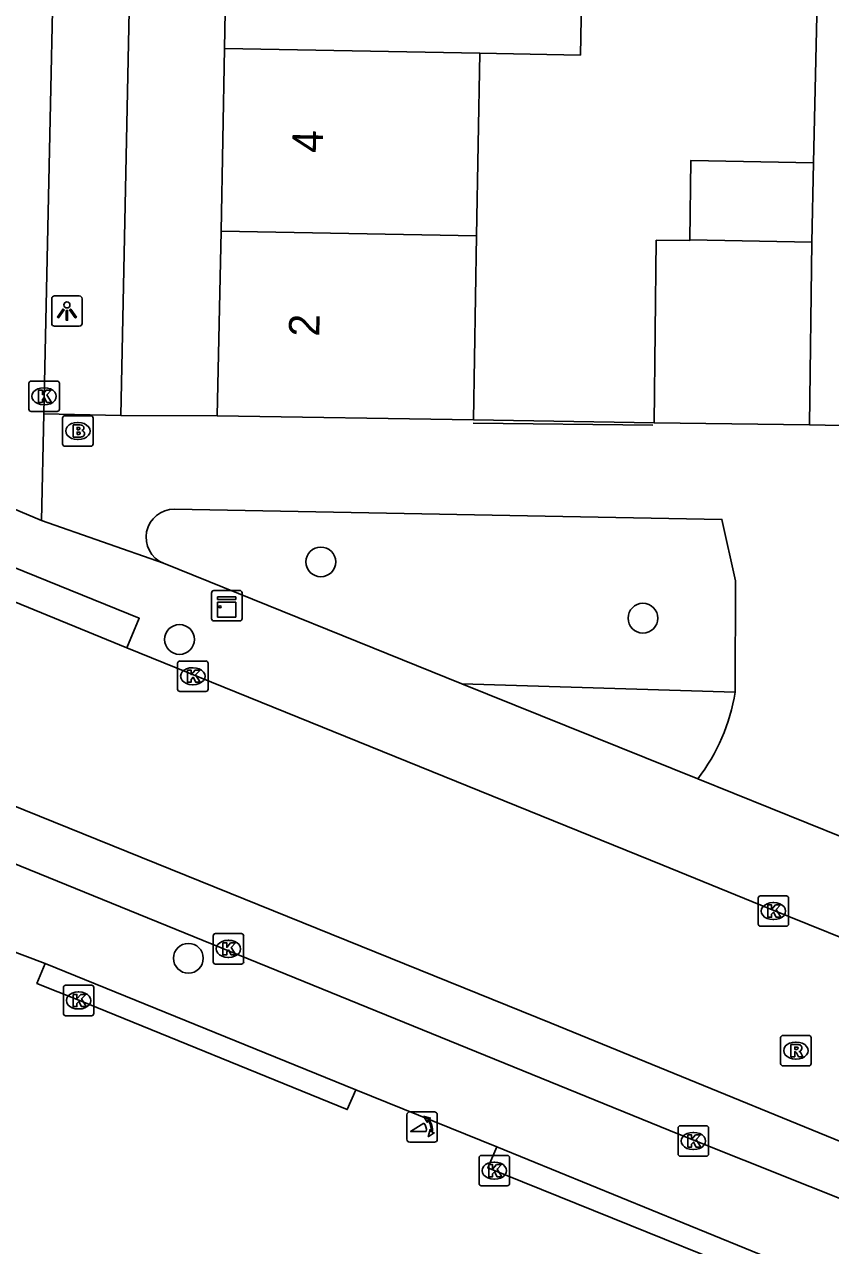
# Model space of a CAD drawing. Extents: x 160026 to 161302, y 384757 to 385701.
# Drawn here: x 160621.17 to 160647.62, y 385019.42 to 385059.5 of the extents above; entities that cross this region are included whole.
import ezdxf

# ---------------------------------------------------------------- set-up
doc = ezdxf.new("R2010")
doc.units = 0
for name, color, linetype in [('IMGEO_Boom', 7, 'Continuous'), ('IMGEO_Brandkraan', 7, 'Continuous'), ('IMGEO_Groenvoorziening', 7, 'Continuous'), ('IMGEO_Haag', 7, 'Continuous'), ('IMGEO_Kast', 7, 'Continuous'), ('IMGEO_Kolk', 7, 'Continuous'), ('IMGEO_Lichtpunt', 7, 'Continuous'), ('IMGEO_Muur', 7, 'Continuous'), ('IMGEO_Pand', 7, 'Continuous'), ('IMGEO_Pand_nummerreeks', 7, 'Continuous'), ('IMGEO_Poller', 7, 'Continuous'), ('IMGEO_Rijbaan_lokaal_gesloten', 7, 'Continuous'), ('IMGEO_Rijbaan_lokaal_open', 7, 'Continuous'), ('IMGEO_Rioolput', 7, 'Continuous'), ('IMGEO_Voetpad_open', 7, 'Continuous')]:
    doc.layers.add(name, color=color, linetype=linetype)

msp = doc.modelspace()

# ---------------------------------------------------------------- linework, layer by layer
at = {"layer": 'IMGEO_Boom'}
for centre in [(160630.895, 385041.857), (160641.464, 385040.01), (160626.26, 385039.312), (160626.55, 385028.846)]:
    msp.add_circle(centre, 0.489, dxfattribs=at)
at = {"layer": 'IMGEO_Brandkraan'}
for p, q in [((160622.425, 385045.729), (160622.425, 385046.581)), ((160622.5, 385046.655), (160623.352, 385046.655)), ((160623.426, 385046.581), (160623.426, 385045.729)), ((160622.913, 385046.435), (160622.938, 385046.435)), ((160622.936, 385045.875), (160622.911, 385045.875)), ((160623.352, 385045.655), (160622.5, 385045.655))]:
    msp.add_line(p, q, dxfattribs=at)
for points in [[(160622.425, 385045.729), (160622.425, 385046.581)], [(160622.5, 385046.655), (160623.352, 385046.655)], [(160623.426, 385046.581), (160623.426, 385045.729)], [(160622.773, 385046.355), (160622.773, 385045.955), (160622.986, 385045.955)], [(160623.004, 385046.355), (160622.773, 385046.355)], [(160622.952, 385046.274), (160622.898, 385046.274), (160622.898, 385046.198)], [(160622.898, 385046.198), (160622.951, 385046.198)], [(160622.96, 385046.122), (160622.898, 385046.122), (160622.898, 385046.041)], [(160622.898, 385046.041), (160622.96, 385046.041)], [(160623.352, 385045.655), (160622.5, 385045.655)]]:
    msp.add_lwpolyline(points, dxfattribs=at)
for centre, radius, start, end in [((160622.502, 385046.579), 0.0765, 91.552, 178.448), ((160622.502, 385046.579), 0.0765, 91.552, 178.448), ((160623.35, 385046.579), 0.0765, 1.552, 88.448), ((160623.35, 385046.579), 0.0765, 1.552, 88.448), ((160622.953, 385046.236), 0.0379, 267.8285, 90.9355), ((160623.008, 385046.21), 0.145, 59.4692, 91.5367), ((160623.033, 385046.257), 0.0922, 285.5137, 58.1501), ((160623.038, 385046.065), 0.105, 301.3115, 78.989), ((160622.961, 385046.081), 0.0404, 269.8759, 90.5077), ((160622.992, 385046.206), 0.251, 268.6676, 293.5347), ((160622.502, 385045.731), 0.0765, 181.552, 268.448), ((160622.502, 385045.731), 0.0765, 181.552, 268.448), ((160623.35, 385045.731), 0.0765, 271.552, 358.448), ((160623.35, 385045.731), 0.0765, 271.552, 358.448)]:
    msp.add_arc(centre, radius, start, end, dxfattribs=at)
for centre, major_axis, ratio, start_param, end_param in [((160622.912, 385046.155), (-0.387, 0.002), 0.722429, 4.712389, 7.853982), ((160622.937, 385046.155), (-0.39, 0.002), 0.717154, 1.570796, 4.712389)]:
    msp.add_ellipse(centre, major_axis=major_axis, ratio=ratio, start_param=start_param, end_param=end_param, dxfattribs=at)
at = {"layer": 'IMGEO_Groenvoorziening'}
msp.add_lwpolyline([(160644.493, 385037.584), (160635.524, 385037.858)], dxfattribs=at)
at = {"layer": 'IMGEO_Haag'}
for points in [[(160632.039, 385024.523), (160631.763, 385023.881), (160622.955, 385027.473), (160621.584, 385028.019), (160621.857, 385028.675)], [(160636.673, 385022.662), (160636.372, 385021.965), (160649.153, 385016.8), (160648.963, 385008.672), (160648.778, 385001.243)]]:
    msp.add_lwpolyline(points, dxfattribs=at)
at = {"layer": 'IMGEO_Kast'}
for p, q in [((160627.311, 385039.994), (160627.311, 385040.835)), ((160627.311, 385040.835), (160627.311, 385039.994)), ((160627.386, 385040.919), (160628.227, 385040.919)), ((160628.227, 385040.919), (160627.386, 385040.919)), ((160628.311, 385040.844), (160628.311, 385040.003)), ((160628.311, 385040.003), (160628.311, 385040.844)), ((160628.236, 385039.919), (160627.395, 385039.919)), ((160627.395, 385039.919), (160628.236, 385039.919))]:
    msp.add_line(p, q, dxfattribs=at)
for points in [[(160627.506, 385040.709), (160628.106, 385040.709), (160628.106, 385040.624), (160627.506, 385040.624), (160627.506, 385040.709)], [(160627.506, 385040.534), (160628.106, 385040.534), (160628.106, 385040.045), (160627.506, 385040.045), (160627.506, 385040.534)]]:
    msp.add_lwpolyline(points, dxfattribs=at)
msp.add_circle((160627.59, 385040.383), 0.0377, dxfattribs=at)
for centre, start, end in [((160627.389, 385040.841), 92.4484, 184.2845), ((160627.389, 385040.841), 92.4484, 184.2845), ((160628.233, 385040.841), 2.4484, 94.2845), ((160628.233, 385040.841), 2.4484, 94.2845), ((160627.389, 385039.997), 182.4484, 274.2845), ((160627.389, 385039.997), 182.4484, 274.2845), ((160628.233, 385039.997), 272.4484, 4.2845), ((160628.233, 385039.997), 272.4484, 4.2845)]:
    msp.add_arc(centre, 0.0779, start, end, dxfattribs=at)
at = {"layer": 'IMGEO_Kolk'}
for p, q in [((160621.391, 385047.795), (160622.243, 385047.795)), ((160621.316, 385046.869), (160621.316, 385047.721)), ((160621.804, 385047.575), (160621.829, 385047.575)), ((160622.317, 385047.721), (160622.317, 385046.869)), ((160621.827, 385047.015), (160621.802, 385047.015)), ((160622.243, 385046.795), (160621.391, 385046.795)), ((160626.197, 385037.679), (160626.197, 385038.531)), ((160626.272, 385038.605), (160627.124, 385038.605)), ((160627.198, 385038.531), (160627.198, 385037.679)), ((160626.685, 385038.385), (160626.71, 385038.385)), ((160626.708, 385037.825), (160626.683, 385037.825)), ((160627.124, 385037.605), (160626.272, 385037.605)), ((160645.242, 385029.97), (160645.242, 385030.822)), ((160645.317, 385030.896), (160646.169, 385030.896)), ((160645.73, 385030.676), (160645.755, 385030.676)), ((160646.243, 385030.822), (160646.243, 385029.97)), ((160645.753, 385030.116), (160645.728, 385030.116)), ((160646.169, 385029.896), (160645.317, 385029.896)), ((160627.363, 385028.73), (160627.363, 385029.582)), ((160627.438, 385029.656), (160628.29, 385029.656)), ((160627.851, 385029.436), (160627.876, 385029.436)), ((160628.364, 385029.582), (160628.364, 385028.73)), ((160628.29, 385028.656), (160627.438, 385028.656)), ((160627.874, 385028.876), (160627.849, 385028.876)), ((160622.448, 385027.036), (160622.448, 385027.888)), ((160622.523, 385027.962), (160623.375, 385027.962)), ((160622.936, 385027.742), (160622.961, 385027.742)), ((160623.449, 385027.888), (160623.449, 385027.036)), ((160623.375, 385026.962), (160622.523, 385026.962)), ((160622.959, 385027.182), (160622.934, 385027.182)), ((160642.691, 385023.349), (160643.543, 385023.349)), ((160642.616, 385022.423), (160642.616, 385023.275)), ((160643.104, 385023.129), (160643.129, 385023.129)), ((160643.617, 385023.275), (160643.617, 385022.423)), ((160643.127, 385022.569), (160643.102, 385022.569)), ((160636.086, 385021.451), (160636.086, 385022.303)), ((160636.161, 385022.377), (160637.013, 385022.377)), ((160636.574, 385022.157), (160636.599, 385022.157)), ((160637.087, 385022.303), (160637.087, 385021.451)), ((160643.543, 385022.349), (160642.691, 385022.349)), ((160637.013, 385021.377), (160636.161, 385021.377)), ((160636.597, 385021.597), (160636.572, 385021.597))]:
    msp.add_line(p, q, dxfattribs=at)
for points in [[(160621.391, 385047.795), (160622.243, 385047.795)], [(160621.316, 385046.869), (160621.316, 385047.721)], [(160621.637, 385047.495), (160621.76, 385047.495), (160621.76, 385047.344), (160621.89, 385047.495), (160622.054, 385047.495), (160621.908, 385047.344), (160622.061, 385047.095), (160621.909, 385047.095), (160621.824, 385047.259), (160621.76, 385047.192), (160621.76, 385047.095), (160621.637, 385047.095), (160621.637, 385047.495)], [(160622.317, 385047.721), (160622.317, 385046.869)], [(160622.243, 385046.795), (160621.391, 385046.795)], [(160626.197, 385037.679), (160626.197, 385038.531)], [(160626.272, 385038.605), (160627.124, 385038.605)], [(160627.198, 385038.531), (160627.198, 385037.679)], [(160626.518, 385038.305), (160626.641, 385038.305), (160626.641, 385038.154), (160626.771, 385038.305), (160626.935, 385038.305), (160626.789, 385038.154), (160626.942, 385037.905), (160626.79, 385037.905), (160626.705, 385038.069), (160626.641, 385038.002), (160626.641, 385037.905), (160626.518, 385037.905), (160626.518, 385038.305)], [(160627.124, 385037.605), (160626.272, 385037.605)], [(160645.242, 385029.97), (160645.242, 385030.822)], [(160645.317, 385030.896), (160646.169, 385030.896)], [(160645.563, 385030.596), (160645.686, 385030.596), (160645.686, 385030.445), (160645.816, 385030.596), (160645.98, 385030.596), (160645.834, 385030.445), (160645.987, 385030.196), (160645.835, 385030.196), (160645.75, 385030.36), (160645.686, 385030.293), (160645.686, 385030.196), (160645.563, 385030.196), (160645.563, 385030.596)], [(160646.243, 385030.822), (160646.243, 385029.97)], [(160646.169, 385029.896), (160645.317, 385029.896)], [(160627.363, 385028.73), (160627.363, 385029.582)], [(160627.438, 385029.656), (160628.29, 385029.656)], [(160627.684, 385029.356), (160627.807, 385029.356), (160627.807, 385029.205), (160627.937, 385029.356), (160628.101, 385029.356), (160627.955, 385029.205), (160628.108, 385028.956), (160627.956, 385028.956), (160627.871, 385029.12), (160627.807, 385029.053), (160627.807, 385028.956), (160627.684, 385028.956), (160627.684, 385029.356)], [(160628.364, 385029.582), (160628.364, 385028.73)], [(160628.29, 385028.656), (160627.438, 385028.656)], [(160622.448, 385027.036), (160622.448, 385027.888)], [(160622.523, 385027.962), (160623.375, 385027.962)], [(160623.449, 385027.888), (160623.449, 385027.036)], [(160622.769, 385027.662), (160622.892, 385027.662), (160622.892, 385027.511), (160623.022, 385027.662), (160623.186, 385027.662), (160623.04, 385027.511), (160623.193, 385027.262), (160623.041, 385027.262), (160622.956, 385027.426), (160622.892, 385027.359), (160622.892, 385027.262), (160622.769, 385027.262), (160622.769, 385027.662)], [(160623.375, 385026.962), (160622.523, 385026.962)], [(160642.691, 385023.349), (160643.543, 385023.349)], [(160642.616, 385022.423), (160642.616, 385023.275)], [(160642.937, 385023.049), (160643.06, 385023.049), (160643.06, 385022.898), (160643.19, 385023.049), (160643.354, 385023.049), (160643.208, 385022.898), (160643.361, 385022.649), (160643.209, 385022.649), (160643.124, 385022.813), (160643.06, 385022.746), (160643.06, 385022.649), (160642.937, 385022.649), (160642.937, 385023.049)], [(160643.617, 385023.275), (160643.617, 385022.423)], [(160636.086, 385021.451), (160636.086, 385022.303)], [(160636.161, 385022.377), (160637.013, 385022.377)], [(160637.087, 385022.303), (160637.087, 385021.451)], [(160643.543, 385022.349), (160642.691, 385022.349)], [(160636.407, 385022.077), (160636.53, 385022.077), (160636.53, 385021.926), (160636.66, 385022.077), (160636.824, 385022.077), (160636.678, 385021.926), (160636.831, 385021.677), (160636.679, 385021.677), (160636.594, 385021.841), (160636.53, 385021.774), (160636.53, 385021.677), (160636.407, 385021.677), (160636.407, 385022.077)], [(160637.013, 385021.377), (160636.161, 385021.377)]]:
    msp.add_lwpolyline(points, dxfattribs=at)
for centre, start, end in [((160621.393, 385047.719), 91.552, 178.448), ((160621.393, 385047.719), 91.552, 178.448), ((160622.241, 385047.719), 1.552, 88.448), ((160622.241, 385047.719), 1.552, 88.448), ((160621.393, 385046.871), 181.552, 268.448), ((160621.393, 385046.871), 181.552, 268.448), ((160622.241, 385046.871), 271.552, 358.448), ((160622.241, 385046.871), 271.552, 358.448), ((160626.274, 385038.529), 91.552, 178.448), ((160626.274, 385038.529), 91.552, 178.448), ((160627.122, 385038.529), 1.552, 88.448), ((160627.122, 385038.529), 1.552, 88.448), ((160626.274, 385037.681), 181.552, 268.448), ((160626.274, 385037.681), 181.552, 268.448), ((160627.122, 385037.681), 271.552, 358.448), ((160627.122, 385037.681), 271.552, 358.448), ((160645.319, 385030.82), 91.552, 178.448), ((160645.319, 385030.82), 91.552, 178.448), ((160646.167, 385030.82), 1.552, 88.448), ((160646.167, 385030.82), 1.552, 88.448), ((160645.319, 385029.972), 181.552, 268.448), ((160645.319, 385029.972), 181.552, 268.448), ((160646.167, 385029.972), 271.552, 358.448), ((160646.167, 385029.972), 271.552, 358.448), ((160627.44, 385029.58), 91.552, 178.448), ((160627.44, 385029.58), 91.552, 178.448), ((160628.288, 385029.58), 1.552, 88.448), ((160628.288, 385029.58), 1.552, 88.448), ((160627.44, 385028.732), 181.552, 268.448), ((160627.44, 385028.732), 181.552, 268.448), ((160628.288, 385028.732), 271.552, 358.448), ((160628.288, 385028.732), 271.552, 358.448), ((160622.525, 385027.886), 91.552, 178.448), ((160622.525, 385027.886), 91.552, 178.448), ((160623.373, 385027.886), 1.552, 88.448), ((160623.373, 385027.886), 1.552, 88.448), ((160622.525, 385027.038), 181.552, 268.448), ((160622.525, 385027.038), 181.552, 268.448), ((160623.373, 385027.038), 271.552, 358.448), ((160623.373, 385027.038), 271.552, 358.448), ((160642.693, 385023.273), 91.552, 178.448), ((160642.693, 385023.273), 91.552, 178.448), ((160643.541, 385023.273), 1.552, 88.448), ((160643.541, 385023.273), 1.552, 88.448), ((160636.163, 385022.301), 91.552, 178.448), ((160636.163, 385022.301), 91.552, 178.448), ((160637.011, 385022.301), 1.552, 88.448), ((160637.011, 385022.301), 1.552, 88.448), ((160642.693, 385022.425), 181.552, 268.448), ((160642.693, 385022.425), 181.552, 268.448), ((160643.541, 385022.425), 271.552, 358.448), ((160643.541, 385022.425), 271.552, 358.448), ((160636.163, 385021.453), 181.552, 268.448), ((160636.163, 385021.453), 181.552, 268.448), ((160637.011, 385021.453), 271.552, 358.448), ((160637.011, 385021.453), 271.552, 358.448)]:
    msp.add_arc(centre, 0.0765, start, end, dxfattribs=at)
for centre, major_axis, ratio, start_param, end_param in [((160621.803, 385047.295), (-0.387, 0.002), 0.722429, 4.712389, 7.853982), ((160621.828, 385047.295), (-0.39, 0.002), 0.717154, 1.570796, 4.712389), ((160626.684, 385038.105), (-0.387, 0.002), 0.722429, 4.712389, 7.853982), ((160626.709, 385038.105), (-0.39, 0.002), 0.717154, 1.570796, 4.712389), ((160645.729, 385030.396), (-0.387, 0.002), 0.722429, 4.712389, 7.853982), ((160645.754, 385030.396), (-0.39, 0.002), 0.717154, 1.570796, 4.712389), ((160627.85, 385029.156), (-0.387, 0.002), 0.722429, 4.712389, 7.853982), ((160627.875, 385029.156), (-0.39, 0.002), 0.717154, 1.570796, 4.712389), ((160622.935, 385027.462), (-0.387, 0.002), 0.722429, 4.712389, 7.853982), ((160622.96, 385027.462), (-0.39, 0.002), 0.717154, 1.570796, 4.712389), ((160643.103, 385022.849), (-0.387, 0.002), 0.722429, 4.712389, 7.853982), ((160643.128, 385022.849), (-0.39, 0.002), 0.717154, 1.570796, 4.712389), ((160636.573, 385021.877), (-0.387, 0.002), 0.722429, 4.712389, 7.853982), ((160636.598, 385021.877), (-0.39, 0.002), 0.717154, 1.570796, 4.712389)]:
    msp.add_ellipse(centre, major_axis=major_axis, ratio=ratio, start_param=start_param, end_param=end_param, dxfattribs=at)
at = {"layer": 'IMGEO_Lichtpunt'}
for p, q in [((160622.969, 385050.591), (160622.161, 385050.591)), ((160622.969, 385050.591), (160622.161, 385050.591)), ((160622.067, 385050.496), (160622.067, 385049.689)), ((160622.067, 385050.496), (160622.067, 385049.689)), ((160623.063, 385049.689), (160623.063, 385050.496)), ((160623.063, 385049.689), (160623.063, 385050.496)), ((160622.161, 385049.595), (160622.969, 385049.595)), ((160622.161, 385049.595), (160622.969, 385049.595))]:
    msp.add_line(p, q, dxfattribs=at)
for points in [[(160622.441, 385050.16), (160622.48, 385050.132), (160622.292, 385049.87), (160622.254, 385049.897), (160622.441, 385050.16)], [(160622.653, 385050.132), (160622.691, 385050.159), (160622.878, 385049.897), (160622.839, 385049.869), (160622.653, 385050.132)], [(160622.543, 385050.112), (160622.59, 385050.112), (160622.59, 385049.79), (160622.543, 385049.79), (160622.543, 385050.112)]]:
    msp.add_lwpolyline(points, dxfattribs=at)
msp.add_circle((160622.566, 385050.294), 0.0994, dxfattribs=at)
for centre, start, end in [((160622.161, 385050.496), 90, 180), ((160622.161, 385050.496), 90, 180), ((160622.969, 385050.496), 0, 90), ((160622.969, 385050.496), 0, 90), ((160622.161, 385049.689), 180, 270), ((160622.161, 385049.689), 180, 270), ((160622.969, 385049.689), 270, 0), ((160622.969, 385049.689), 270, 360)]:
    msp.add_arc(centre, 0.0946, start, end, dxfattribs=at)
at = {"layer": 'IMGEO_Muur'}
msp.add_lwpolyline([(160641.787, 385046.351), (160635.89, 385046.412)], dxfattribs=at)
at = {"layer": 'IMGEO_Pand'}
for points in [[(160627.739, 385058.707), (160627.849, 385064.704)], [(160636.224, 385064.55), (160639.522, 385064.489), (160639.412, 385058.492), (160636.114, 385058.553)], [(160627.628, 385052.71), (160627.739, 385058.707)], [(160627.739, 385058.707), (160636.114, 385058.553)], [(160636.114, 385058.553), (160636.003, 385052.556)], [(160643.001, 385052.427), (160643.034, 385055.029), (160647.056, 385054.955)], [(160647.056, 385054.955), (160647.008, 385052.354)], [(160627.628, 385052.71), (160627.498, 385046.657)], [(160636.003, 385052.556), (160627.628, 385052.71)], [(160635.899, 385046.526), (160636.003, 385052.556)], [(160643.001, 385052.427), (160643.001, 385052.403), (160641.899, 385052.417), (160641.833, 385046.422)], [(160647.008, 385052.354), (160643.001, 385052.427)], [(160647.008, 385052.354), (160646.931, 385046.352)], [(160635.899, 385046.526), (160627.498, 385046.657)], [(160641.833, 385046.422), (160646.931, 385046.352)]]:
    msp.add_lwpolyline(points, dxfattribs=at)
at = {"layer": 'IMGEO_Poller'}
for p, q in [((160633.719, 385023.711), (160633.719, 385022.904)), ((160633.719, 385023.711), (160633.719, 385022.904)), ((160634.621, 385023.806), (160633.813, 385023.806)), ((160634.621, 385023.806), (160633.813, 385023.806)), ((160634.715, 385022.904), (160634.715, 385023.711)), ((160634.715, 385022.904), (160634.715, 385023.711)), ((160633.813, 385022.809), (160634.621, 385022.809)), ((160633.813, 385022.809), (160634.621, 385022.809))]:
    msp.add_line(p, q, dxfattribs=at)
for points in [[(160634.354, 385023.162), (160633.841, 385023.162), (160634.271, 385023.437)], [(160634.398, 385023.535), (160634.386, 385023.462), (160634.261, 385023.667)], [(160634.261, 385023.667), (160634.492, 385023.601), (160634.421, 385023.569)], [(160634.414, 385022.99), (160634.48, 385023.221), (160634.51, 385023.153)], [(160634.546, 385023.126), (160634.618, 385023.115), (160634.414, 385022.99)]]:
    msp.add_lwpolyline(points, dxfattribs=at)
for centre, radius, start, end in [((160633.813, 385023.711), 0.0946, 90, 180), ((160633.813, 385023.711), 0.0946, 90, 180), ((160634.621, 385023.711), 0.0946, 0, 90), ((160634.621, 385023.711), 0.0946, 0, 90), ((160634.026, 385023.212), 0.332, 351.3247, 42.4854), ((160634.04, 385023.222), 0.476, 351.7527, 41.1691), ((160634.04, 385023.222), 0.516, 349.3569, 42.2912), ((160633.813, 385022.904), 0.0946, 180, 270), ((160633.813, 385022.904), 0.0946, 180, 270), ((160634.621, 385022.904), 0.0946, 270, 0), ((160634.621, 385022.904), 0.0946, 270, 0)]:
    msp.add_arc(centre, radius, start, end, dxfattribs=at)
at = {"layer": 'IMGEO_Rijbaan_lokaal_gesloten'}
for points in [[(160564.76, 385054.855), (160567.998, 385054.013), (160577.194, 385051.171), (160585.082, 385048.283), (160588.849, 385046.836), (160596.698, 385043.67), (160620.694, 385033.909), (160638.453, 385026.712), (160665.07, 385015.82)], [(160624.532, 385039.041), (160612.845, 385043.826)], [(160667.501, 385021.654), (160664.82, 385022.747), (160662.491, 385023.66), (160645.566, 385030.496), (160642.12, 385031.906), (160624.532, 385039.041)]]:
    msp.add_lwpolyline(points, dxfattribs=at)
at = {"layer": 'IMGEO_Rijbaan_lokaal_open'}
for points in [[(160622.965, 385101.188), (160622.916, 385099.184), (160622.325, 385070.649), (160621.803, 385046.719)], [(160615.997, 385050.184), (160615.918, 385045.67), (160621.727, 385043.212)], [(160621.803, 385046.719), (160621.727, 385043.212)]]:
    msp.add_lwpolyline(points, dxfattribs=at)
at = {"layer": 'IMGEO_Rioolput'}
for p, q in [((160645.981, 385025.389), (160645.981, 385026.241)), ((160646.056, 385026.315), (160646.908, 385026.315)), ((160646.982, 385026.241), (160646.982, 385025.389)), ((160646.469, 385026.095), (160646.494, 385026.095)), ((160646.908, 385025.315), (160646.056, 385025.315)), ((160646.492, 385025.535), (160646.467, 385025.535))]:
    msp.add_line(p, q, dxfattribs=at)
for points in [[(160645.981, 385025.389), (160645.981, 385026.241)], [(160646.056, 385026.315), (160646.908, 385026.315)], [(160646.982, 385026.241), (160646.982, 385025.389)], [(160646.57, 385026.013), (160646.318, 385026.015), (160646.318, 385025.615)], [(160646.318, 385025.615), (160646.442, 385025.615), (160646.442, 385025.777), (160646.453, 385025.777)], [(160646.496, 385025.934), (160646.442, 385025.934), (160646.442, 385025.853)], [(160646.442, 385025.853), (160646.494, 385025.853)], [(160646.5, 385025.748), (160646.571, 385025.615), (160646.711, 385025.615), (160646.646, 385025.741)], [(160646.908, 385025.315), (160646.056, 385025.315)]]:
    msp.add_lwpolyline(points, dxfattribs=at)
for centre, radius, start, end in [((160646.058, 385026.239), 0.0765, 91.552, 178.448), ((160646.058, 385026.239), 0.0765, 91.552, 178.448), ((160646.906, 385026.239), 0.0765, 1.552, 88.448), ((160646.906, 385026.239), 0.0765, 1.552, 88.448), ((160646.452, 385025.724), 0.0533, 26.0293, 88.6989), ((160646.478, 385026.042), 0.19, 274.7715, 282.9687), ((160646.502, 385025.838), 0.0964, 77.0061, 93.1865), ((160646.516, 385025.895), 0.0378, 276.6634, 79.6772), ((160646.569, 385025.903), 0.109, 350.3612, 89.416), ((160646.567, 385025.903), 0.112, 277.5842, 350.9817), ((160646.551, 385025.688), 0.108, 29.5134, 73.7905), ((160646.058, 385025.391), 0.0765, 181.552, 268.448), ((160646.058, 385025.391), 0.0765, 181.552, 268.448), ((160646.906, 385025.391), 0.0765, 271.552, 358.448), ((160646.906, 385025.391), 0.0765, 271.552, 358.448)]:
    msp.add_arc(centre, radius, start, end, dxfattribs=at)
for centre, major_axis, ratio, start_param, end_param in [((160646.468, 385025.815), (-0.387, 0.002), 0.722429, 4.712389, 7.853982), ((160646.493, 385025.815), (-0.39, 0.002), 0.717154, 1.570796, 4.712389)]:
    msp.add_ellipse(centre, major_axis=major_axis, ratio=ratio, start_param=start_param, end_param=end_param, dxfattribs=at)
at = {"layer": 'IMGEO_Voetpad_open'}
for points in [[(160625.445, 385100.857), (160624.337, 385046.664)], [(160647.208, 385061.732), (160647.056, 385054.955)], [(160566.863, 385052.545), (160571.301, 385051.19), (160585.387, 385046.34), (160611.75, 385035.652), (160642.612, 385023.087), (160657.707, 385017.06), (160664.436, 385014.299)], [(160624.337, 385046.664), (160621.803, 385046.719)], [(160627.498, 385046.657), (160624.337, 385046.664)], [(160641.833, 385046.422), (160635.899, 385046.526)], [(160646.931, 385046.352), (160648.462, 385046.325)], [(160624.532, 385039.041), (160624.936, 385040.01), (160613.259, 385044.754), (160612.845, 385043.826)], [(160626.097, 385043.587), (160644.053, 385043.251), (160644.504, 385041.234), (160644.493, 385037.584)], [(160621.727, 385043.212), (160625.737, 385041.812)], [(160625.737, 385041.812), (160635.524, 385037.858)], [(160635.524, 385037.858), (160643.261, 385034.732)], [(160643.261, 385034.732), (160648.029, 385032.808)], [(160619.435, 385029.588), (160621.857, 385028.675)], [(160621.857, 385028.675), (160632.039, 385024.523)], [(160632.039, 385024.523), (160636.673, 385022.662)], [(160649.88, 385016.945), (160649.888, 385017.253), (160636.673, 385022.662)]]:
    msp.add_lwpolyline(points, dxfattribs=at)
for centre, radius, start, end in [((160626.082, 385042.666), 0.921, 89.0472, 248.0227), ((160638.143, 385038.635), 6.437, 322.6716, 350.6019)]:
    msp.add_arc(centre, radius, start, end, dxfattribs=at)

# ---------------------------------------------------------------- texts
at = {"layer": 'IMGEO_Pand_nummerreeks'}
for s, rotation, p in [('4', 88.9445, (160630.956, 385055.277)), ('2', 88.946, (160630.845, 385049.245))]:
    msp.add_text(s, height=1, rotation=rotation, dxfattribs=at).set_placement(p)

doc.saveas('drawing.dxf')
